
// ===== library: MasterCopy "BVS_SC" =====

FUNCTION_BLOCK "BVS_SC"   // FB50, SCL
TITLE = BVS_SC
{ S7_Optimized_Access := 'FALSE' }
AUTHOR : BI-CU
FAMILY : Balluff
VERSION : 1.4
BEGIN
END_FUNCTION_BLOCK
